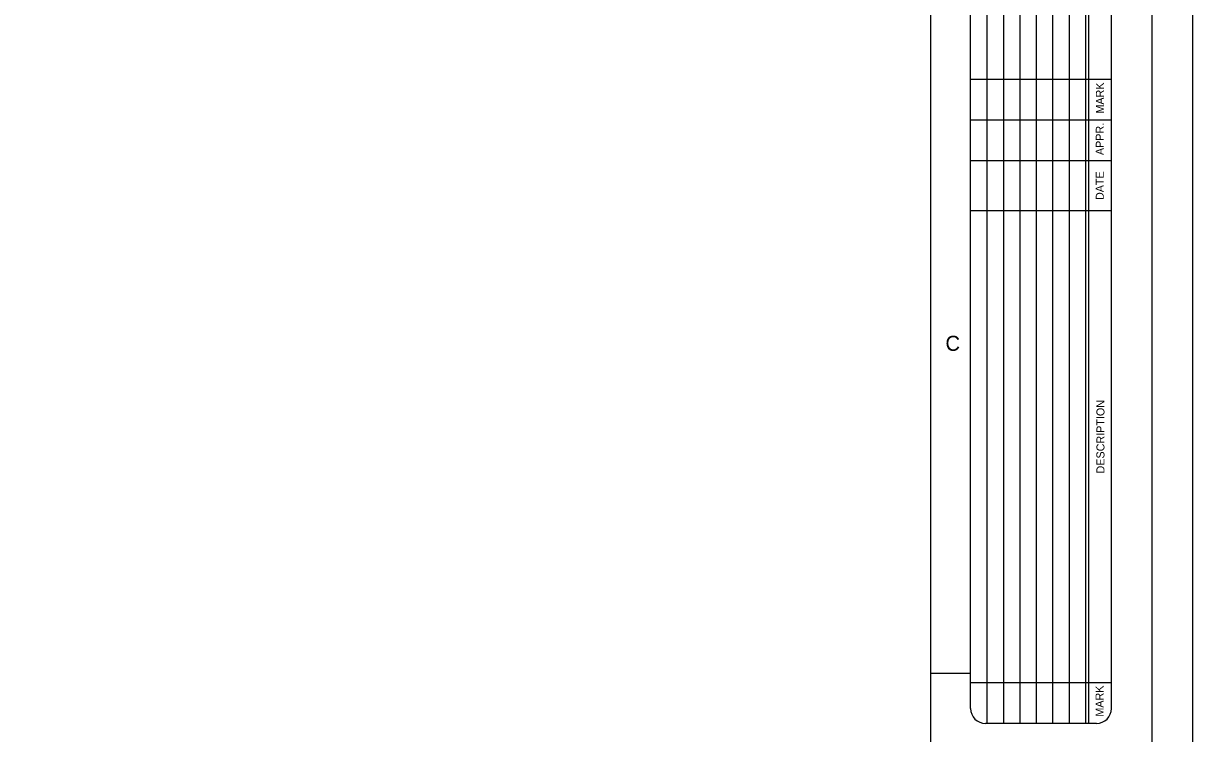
# Model space of a CAD drawing. Extents: x 22411.4 to 22495.4, y 22369.6 to 22415.
# Drawn here: x 22476.01 to 22495.39, y 22391.29 to 22403.06 of the extents above; entities that cross this region are included whole.
import ezdxf

# ---------------------------------------------------------------- set-up
doc = ezdxf.new("R2010")
doc.units = 0
for name, color, linetype in [('Level 1', 7, 'Continuous'), ('Level 10', 7, 'Continuous'), ('Level 7', 7, 'Continuous'), ('Level 9', 7, 'Continuous')]:
    doc.layers.add(name, color=color, linetype=linetype)

msp = doc.modelspace()

# ---------------------------------------------------------------- linework, layer by layer
at = {"layer": 'Level 1'}
for p, q in [((22491.982, 22411.461), (22491.982, 22391.461)), ((22492.254, 22411.461), (22492.254, 22391.461)), ((22492.526, 22411.461), (22492.526, 22391.461)), ((22492.798, 22411.461), (22492.798, 22391.461)), ((22493.07, 22411.461), (22493.07, 22391.461)), ((22493.342, 22411.461), (22493.342, 22391.461)), ((22493.614, 22411.461), (22493.614, 22391.461)), ((22493.662, 22411.461), (22493.662, 22391.461)), ((22494.046, 22401.461), (22491.71, 22401.461)), ((22493.796, 22391.461), (22491.96, 22391.461))]:
    msp.add_line(p, q, dxfattribs=at)
msp.add_lwpolyline([(22436.723, 22414.965), (22495.39, 22414.965), (22495.39, 22369.621), (22436.723, 22369.621)], close=True, dxfattribs=at)
for points in [[(22491.71, 22391.711), (22491.71, 22411.211)], [(22494.046, 22391.711), (22494.046, 22411.211)]]:
    msp.add_lwpolyline(points, dxfattribs=at)
for centre, start, end in [((22491.96, 22391.711), 180, 270), ((22493.796, 22391.711), 270, 0)]:
    msp.add_arc(centre, 0.25, start, end, dxfattribs=at)
at = {"layer": 'Level 10'}
msp.add_line((22491.054, 22392.293), (22491.71, 22392.293), dxfattribs=at)
at = {"layer": 'Level 7'}
for p, q in [((22494.046, 22400.789), (22491.71, 22400.789)), ((22494.046, 22399.956), (22491.71, 22399.956)), ((22494.046, 22392.133), (22491.71, 22392.133))]:
    msp.add_line(p, q, dxfattribs=at)
msp.add_lwpolyline([(22494.046, 22402.133), (22491.71, 22402.133)], dxfattribs=at)
at = {"layer": 'Level 9'}
msp.add_line((22494.718, 22370.293), (22494.718, 22414.293), dxfattribs=at)
msp.add_lwpolyline([(22491.054, 22370.293), (22491.054, 22414.293)], dxfattribs=at)

# ---------------------------------------------------------------- texts
at = {"layer": 'Level 1'}
for s, height, p in [('MARK', 0.1333, (22493.921, 22401.57)), ('APPR.', 0.1333, (22493.918, 22400.882)), ('DATE', 0.1333, (22493.918, 22400.137)), ('DESCRIPTION', 0.13333, (22493.929, 22395.605)), ('MARK', 0.1333, (22493.914, 22391.575))]:
    msp.add_text(s, height=height, rotation=90, dxfattribs=at).set_placement(p)
msp.add_text('C', height=0.25, dxfattribs=at).set_placement((22491.294, 22397.637))

doc.saveas('drawing.dxf')
